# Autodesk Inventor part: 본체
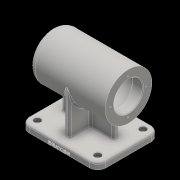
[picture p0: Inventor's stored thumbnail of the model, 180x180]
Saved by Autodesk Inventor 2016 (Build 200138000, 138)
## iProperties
Created: 2020-10
Part Number: 본체
Material: 일반
Document SubType Name: Modeling
Designer: 605-04
Density: 1 g/cm^3
Appearance: 기본값
Author: 605-04
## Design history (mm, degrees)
sketch "스케치1"
  geometry: L1 (0, 0)-(0, 34); L2 (0, 34)-(112, 34); L3 (112, 34)-(112, 0); L4 (112, 0)-(0, 0); L5 (6, 0)-(6, 10.5); L6 (6, 10.5)-(9, 10.5); L7 (9, 10.5)-(9, 16); L8 (9, 16)-(13, 16); L9 (13, 16)-(13, 17.5); L10 (13, 17.5)-(31, 17.5); L11 (31, 17.5)-(31, 21); L12 (31, 21)-(43, 21); L13 (43, 21)-(43, 24); L14 (43, 24)-(97, 24); L15 (97, 24)-(97, 21); L16 (97, 21)-(112, 21)
  constraints: 32 end point, 14 perpendicular, 4 point on line, 1 vertical
  dimensions: "d1" = 21 diameter of L6 L4; "d2" = 32 diameter of L8 L4; "d3" = 35 diameter of L10 L4; "d4" = 42 diameter of L12 L4; "d5" = 48 diameter of L14 L4; "d6" = 3 distance between parallel lines of L7 L5; "d7" = 4 distance between parallel lines of L9 L7; "d8" = 18 distance between parallel lines of L11 L9; "d9" = 12 distance between parallel lines of L13 L11; "d10" = 54 distance between parallel lines of L15 L13; "d11" = 112 distance between parallel lines of L3 L1; "d12" = 15 distance between parallel lines of L3 L15; "d13" = 68 diameter of L2 L4
revolve "회전1" sketch "스케치1" stored, may be unused: angle "d14" = 90 deg
node "작업 평면1"
sketch "스케치2"
  geometry: L1 (112, -45)-(0, -45); L2 (0, -45)-(0, 45); L3 (0, 45)-(112, 45); L4 (112, 45)-(112, -45); L5 (112, -45)-(0, 45); L6 (0, -45)-(112, 45); L7 (112, -34)-(112, 34) reference; 3 further points
  constraints: 12 end point, 3 midpoint, 2 parallel, 1 collinear, 1 horizontal, 1 horizontal alignment, 1 perpendicular
  dimensions: "d16" = 112 distance of L2.end L3.end; "d17" = 90 distance of L3.end L1.start
extrude "돌출1" join sketch "스케치2" distance "d18" = 10; taper "d19" = 0 deg
sketch "스케치3"
  geometry: L1 (112, 45)-(112, -45) reference; L2 (112, -45)-(0, -45) reference; L3 (52, -34)-(60, -34); L4 (60, -34)-(60, 34); L5 (60, 34)-(52, 34); L6 (52, 34)-(52, -34); L7 (52, -34)-(60, 34); L8 (60, -34)-(52, 34); L9 (0, 45)-(112, 45) reference; L10 (18, 4)-(94, 4); L11 (94, 4)-(94, -4); L12 (94, -4)-(18, -4); L13 (18, -4)-(18, 4); L14 (18, 4)-(94, -4); L15 (94, 4)-(18, -4); 2 further points
  constraints: 24 end point, 4 midpoint, 4 parallel, 2 horizontal, 2 perpendicular
  dimensions: "d23" = 56 distance from line of L1 point (56, 0); "d24" = 45 distance from line of L9 point (56, 0); "d25" = 8 distance of L4.end L5.end; "d26" = 68 distance of L3.end L4.end; "d29" = 8 distance of L10.end L11.end; "d30" = 76 distance of L11.end L12.end
extrude "돌출2" join sketch "스케치3" stored distance "d27" = 10; taper "d28" = 0 deg
sketch "스케치4"
  geometry: L1 (0, 0)-(-26, 0); C1 r 34 at (0, 0) reference; C2 r 21 at (0, 0) reference; 1 further point
  constraints: 2 end point, 1 horizontal
  dimensions: "d31" = 26 distance of L1.start L1.end
hole "구멍1" sketch "스케치4" at (-26, 0) diameter "d32" = 3.242; stored, may be unused: countersink angle "d36" = 90 deg, drill point angle "d38" = 118 deg; dims "d33" = 8, "d34" = 4, "d35" = 2, "d37" = 11
sketch "스케치5"
  geometry: L1 (112, -45)-(0, -45) reference; L2 (0, -45)-(0, 45) reference; L3 (0, 45)-(112, 45) reference; L4 (112, 45)-(112, -45) reference; 2 further points
  dimensions: "d42" = 12 distance from line of L1 point (12, -33); "d43" = 12 distance from line of L2 point (12, -33)
hole "구멍2" sketch "스케치5" at (12, -33) diameter "d44" = 5.5; stored, may be unused: countersink angle "d48" = 90 deg, drill point angle "d50" = 118 deg; dims "d45" = 8, "d46" = 9.5, "d47" = 5.4, "d49" = 10
fillet "모깎기1" dims "d57" = 3
fillet "모깎기2" dims "d58" = 12
fillet "모깎기3" dims "d59" = 3
fillet "모깎기4" dims "d60" = 0.3
fillet "모깎기5" dims "d61" = 3
fillet "모깎기6" dims "d62" = 3
chamfer "모따기1" distance "d63" = 1; stored, may be unused: second distance "d64" = 2, angle "d65" = 45 deg
fillet "모깎기7" dims "d66" = 10
sketch "스케치6"
  geometry: L1 (30.079, 4.97)-(57.921, 4.97); L2 (57.921, 4.97)-(57.921, 1.03); L3 (57.921, 1.03)-(30.079, 1.03); L4 (30.079, 1.03)-(30.079, 4.97); L5 (30.079, 3)-(44, 3); L6 (44, 4.97)-(44, 3); L7 (100, 0)-(100, 7) reference; L8 (88, 0)-(0, 0) reference; 1 further point
  constraints: 4 end point, 2 midpoint, 2 other
  dimensions: "d67" = 56 distance from line of L7 L5.end; "d68" = 3 distance between parallel lines of L8 L5
feature "엠보싱1" sketch "스케치6" dims "d1" = 21, "d2" = 32, "d3" = 35, "d4" = 42, "d5" = 48, "d6" = 3, "d7" = 4, "d8" = 18, "d9" = 12, "d10" = 54, "d11" = 112, "d12" = 15, "d13" = 68, "d16" = 112, "d17" = 90, "d69" = 0.5, "d70" = 0
node "솔리드1"
pattern_circular "원형 패턴1" dims angle "d40" = 360 deg
pattern_linear "직사각형 패턴1" dims "d53" = 66, "d56" = 88
node "투영된 루프1"
node "투영된 루프2"
other parameters: "d15" = -74
